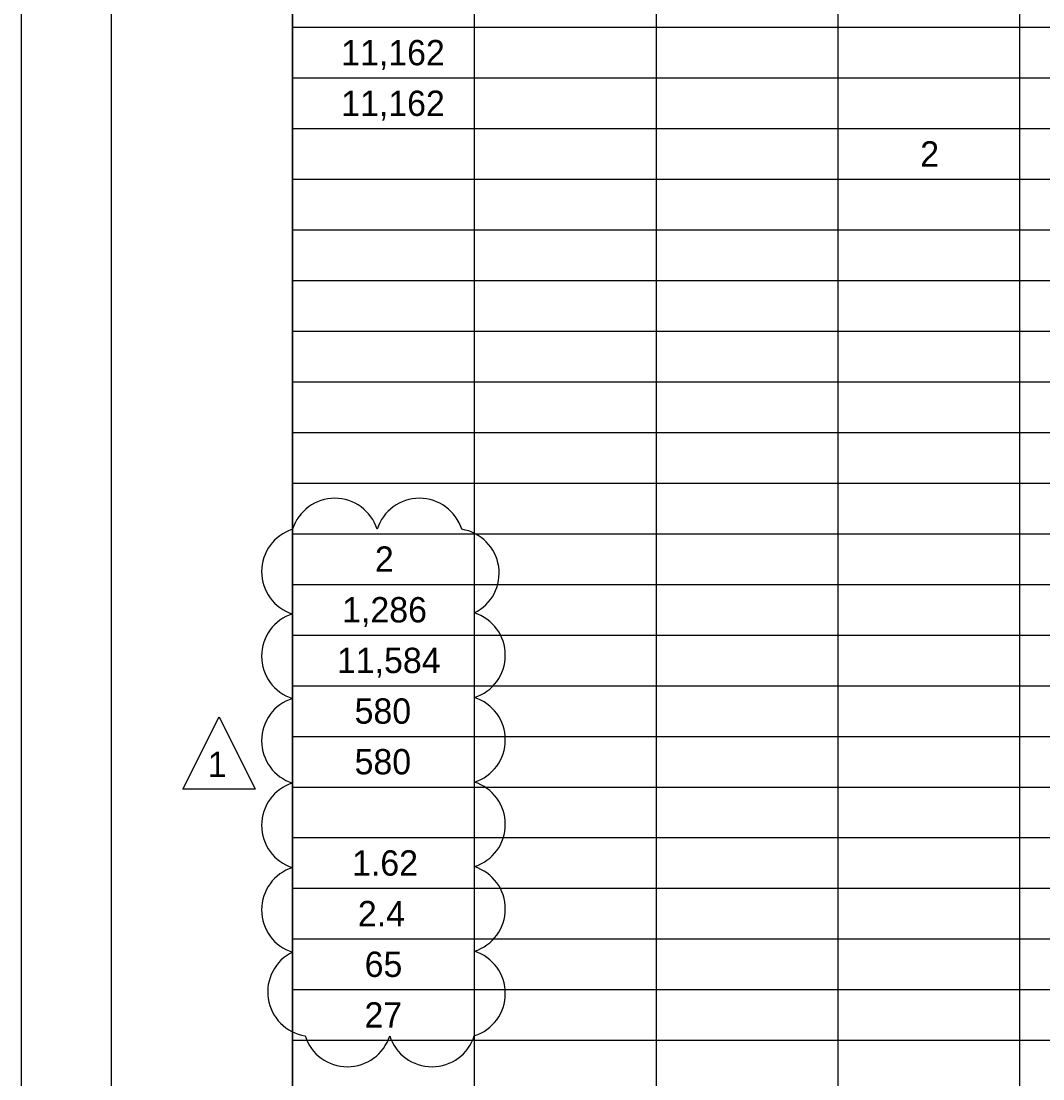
# Model space of a CAD drawing. Extents: x -156 to 77, y 0 to 24.
# Drawn here: x 0 to 5.65, y 10.37 to 16.21 of the extents above; entities that cross this region are included whole.
import ezdxf

# ---------------------------------------------------------------- set-up
doc = ezdxf.new("R2010")
doc.units = 0
for name, color, linetype in [('Default', 7, 'Continuous'), ('MU_Markup_Cloud', 7, 'Continuous'), ('SH_Border', 7, 'Continuous'), ('SH_Cut_Line', 7, 'Continuous')]:
    doc.layers.add(name, color=color, linetype=linetype)

msp = doc.modelspace()

# ---------------------------------------------------------------- linework, layer by layer
at = {"layer": 'Default'}
for p, q in [((1.5, 21.5), (1.5, 0.5)), ((2.5047, 20.94), (2.5047, 0.5)), ((3.5094, 20.94), (3.5094, 0.5)), ((4.5141, 20.94), (4.5141, 0.5)), ((5.5188, 20.94), (5.5188, 0.5)), ((1.5, 16.18), (32.0036, 16.18)), ((1.5, 15.9), (32.0036, 15.9)), ((1.5, 15.62), (32.0036, 15.62)), ((1.5, 15.34), (32.0036, 15.34)), ((1.5, 15.06), (32.0036, 15.06)), ((1.5, 14.78), (32.0036, 14.78)), ((1.5, 14.5), (32.0036, 14.5)), ((1.5, 14.22), (32.0036, 14.22)), ((1.5, 13.94), (32.0036, 13.94)), ((1.5, 13.66), (32.0036, 13.66)), ((1.5, 13.38), (32.0036, 13.38)), ((1.5, 13.1), (32.0036, 13.1)), ((1.5, 12.82), (32.0036, 12.82)), ((1.5, 12.54), (32.0036, 12.54)), ((1.5, 12.26), (32.0036, 12.26)), ((1.5, 11.98), (32.0036, 11.98)), ((1.5, 11.7), (32.0036, 11.7)), ((1.5, 11.42), (32.0036, 11.42)), ((1.5, 11.14), (32.0036, 11.14)), ((1.5, 10.86), (32.0036, 10.86)), ((1.5, 10.58), (32.0036, 10.58))]:
    msp.add_line(p, q, dxfattribs=at)
at = {"layer": 'MU_Markup_Cloud'}
msp.add_lwpolyline([(0.8936, 11.9685), (1.0936, 12.3685), (1.2936, 11.9685)], close=True, dxfattribs=at)
for centre, start, end in [((1.7338, 13.3309), 17.5, 162.5), ((2.2013, 13.3309), 17.5, 162.5), ((1.5737, 13.1708), 107.5, 252.5), ((2.397, 13.1625), 296.06258, 81.06258), ((1.5737, 12.7033), 107.5, 252.5), ((2.431, 12.7086), 287.5, 72.5), ((1.5737, 12.2357), 107.5, 252.5), ((2.431, 12.241), 287.5, 72.5), ((1.5737, 11.7682), 107.5, 252.5), ((2.431, 11.7735), 287.5, 72.5), ((1.5737, 11.3006), 107.5, 252.5), ((2.431, 11.3059), 287.5, 72.5), ((1.6077, 10.8467), 116.06258, 261.06258), ((2.431, 10.8384), 287.5, 72.5), ((1.8034, 10.6783), 197.5, 342.5), ((2.2709, 10.6783), 197.5, 342.5)]:
    msp.add_arc(centre, 0.2451, start, end, dxfattribs=at)
at = {"layer": 'SH_Border'}
for points in [[(0.5, 21.5), (1.5, 21.5), (1.5, 0.5), (0.5, 0.5)], [(1.5, 21.5), (33.5, 21.5), (33.5, 0.5), (1.5, 0.5)]]:
    msp.add_lwpolyline(points, close=True, dxfattribs=at)
at = {"layer": 'SH_Cut_Line'}
msp.add_lwpolyline([(0, 0), (34, 0), (34, 22), (0, 22)], close=True, dxfattribs=at)

# ---------------------------------------------------------------- texts
at = {"layer": 'Default'}
for s, p in [('11,162', (1.7689, 15.97)), ('11,162', (1.7689, 15.69)), ('2', (4.9694, 15.41)), ('2', (1.9552, 13.17)), ('1,286', (1.7744, 12.89)), ('11,584', (1.7456, 12.61)), ('580', (1.843, 12.33)), ('580', (1.843, 12.05)), ('1.62', (1.829, 11.49)), ('2.4', (1.8613, 11.21)), ('65', (1.8986, 10.93)), ('27', (1.8976, 10.65))]:
    msp.add_text(s, height=0.14, dxfattribs=at).set_placement(p)
at = {"layer": 'MU_Markup_Cloud'}
msp.add_text('1', height=0.14, dxfattribs=at).set_placement((1.0308, 12.0346))

doc.saveas('drawing.dxf')
